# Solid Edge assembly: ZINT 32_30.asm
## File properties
Title: Zylinder
Author: bmolnar
Template: iso metric assembly.asm
Last saved by: bmolnar
Revision: 15
Application: Solid Edge
Username: bmolnar
Dokumentum tartalom típus: 1
Document Number: ZINT 32/30
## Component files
hrungsstange.par
Profilrohr.par
Platte.par
Kolbenstange.par
Kit_2.par
Kit_1.par
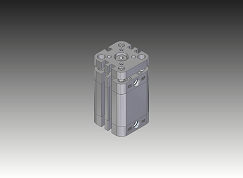
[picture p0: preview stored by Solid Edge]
